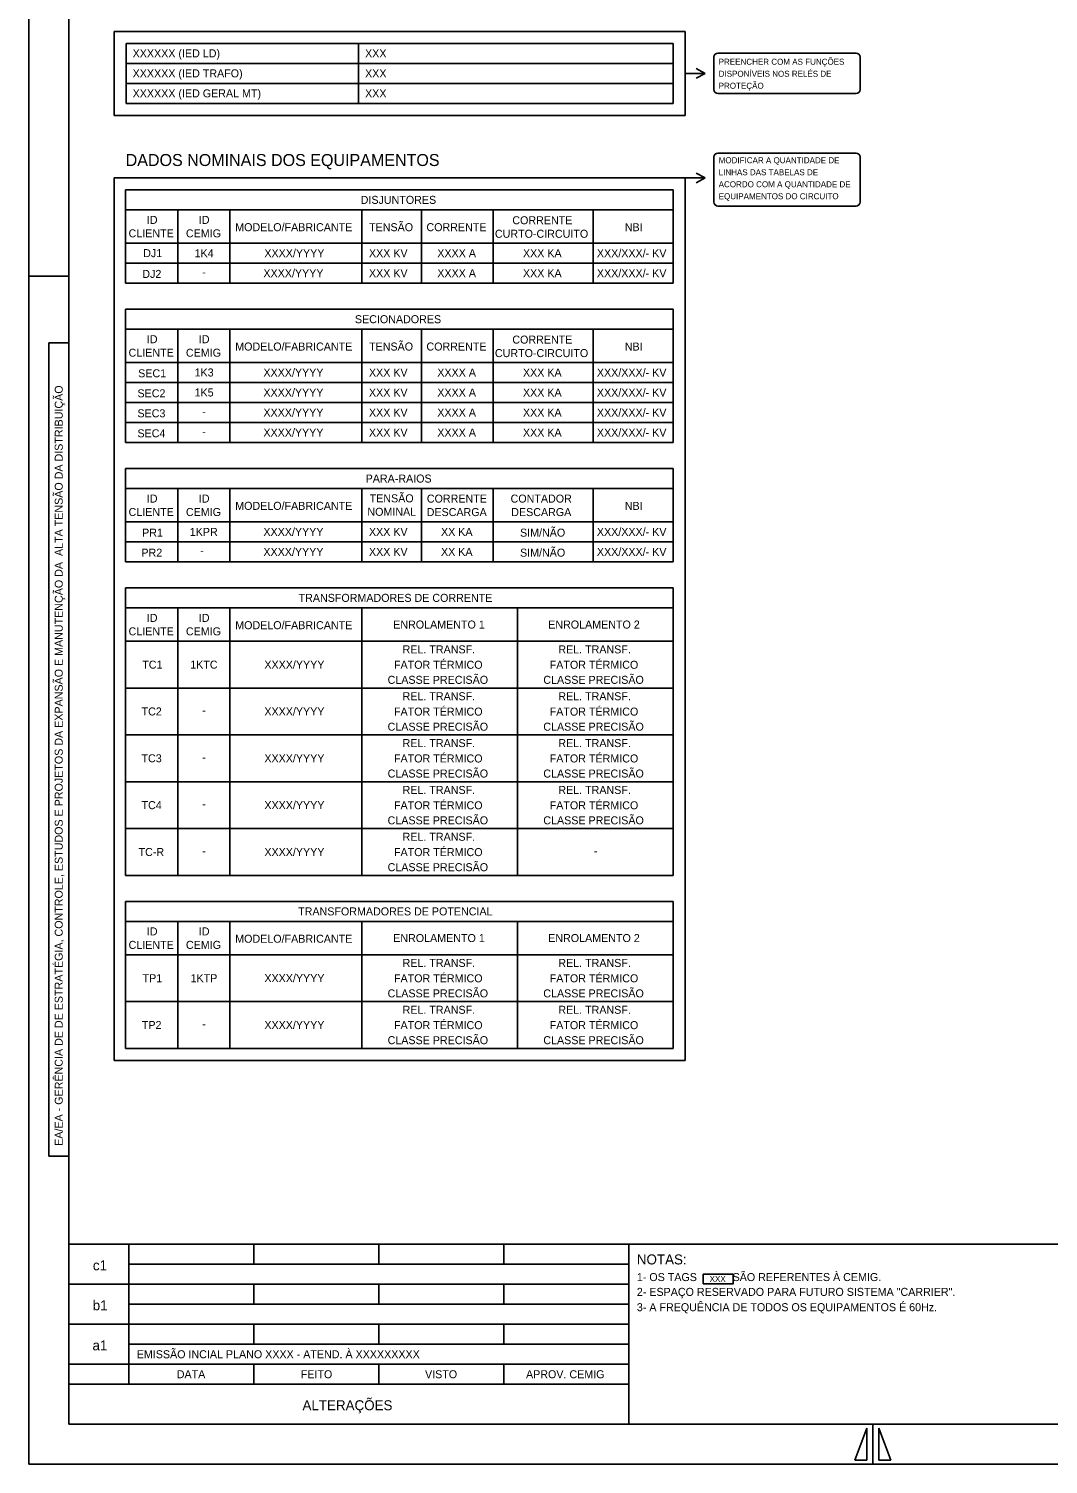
# Model space of a CAD drawing. Extents: x 563 to 1404, y 358 to 952.
# Drawn here: x 562.6 to 817.4, y 358 to 716.8 of the extents above; entities that cross this region are included whole.
import ezdxf

# ---------------------------------------------------------------- set-up
doc = ezdxf.new("R2010")
doc.units = 0
doc.layers.add('New Level (0)', color=7, linetype='Continuous')

# ---------------------------------------------------------------- blocks, each defined once
blk = doc.blocks.new('POINT_DISPLAY')
blk.add_line((0, 0), (0, 0))

msp = doc.modelspace()

# ---------------------------------------------------------------- linework, layer by layer
at = {"layer": 'New Level (0)'}
for p, q in [((562.58, 951.96), (562.58, 357.96)), ((562.58, 951.96), (562.58, 357.96)), ((572.58, 941.96), (572.58, 367.96)), ((572.58, 941.96), (572.58, 367.96)), ((583.96, 716.12), (726.65, 716.12)), ((583.96, 716.12), (583.96, 695.12)), ((726.65, 716.12), (726.65, 695.12)), ((586.96, 713.12), (723.65, 713.12)), ((586.96, 713.12), (586.96, 698.12)), ((645.01, 713.12), (645.01, 698.12)), ((723.65, 713.12), (723.65, 698.12)), ((734.84, 710.67), (742.19, 710.67)), ((742.19, 710.67), (769.38, 710.67)), ((586.96, 708.12), (723.65, 708.12)), ((733.84, 701.56), (733.84, 709.67)), ((770.38, 709.67), (770.38, 701.56)), ((726.65, 705.62), (731.68, 705.62)), ((731.68, 705.62), (729.38, 706.83)), ((731.68, 705.62), (729.38, 704.41)), ((586.96, 703.12), (723.65, 703.12)), ((769.38, 700.56), (734.84, 700.56)), ((586.96, 698.12), (723.65, 698.12)), ((583.96, 695.12), (726.65, 695.12)), ((734.84, 685.7), (742.19, 685.7)), ((742.19, 685.7), (769.38, 685.7)), ((733.84, 673.45), (733.84, 684.7)), ((770.38, 684.7), (770.38, 673.45)), ((583.96, 679.5), (583.96, 458.91)), ((583.96, 679.5), (726.65, 679.5)), ((726.65, 679.5), (726.65, 458.91)), ((726.65, 679.5), (731.68, 679.5)), ((731.68, 679.5), (729.38, 680.71)), ((731.68, 679.5), (729.38, 678.29)), ((586.81, 676.5), (586.81, 653.17)), ((586.81, 676.5), (723.65, 676.5)), ((723.65, 676.5), (723.65, 653.17)), ((723.65, 671.5), (586.81, 671.5)), ((599.81, 671.5), (599.81, 653.17)), ((612.81, 653.17), (612.81, 671.5)), ((645.81, 671.5), (645.81, 653.17)), ((660.72, 671.5), (660.72, 653.17)), ((678.66, 671.5), (678.66, 653.17)), ((703.66, 671.5), (703.66, 653.17)), ((769.38, 672.45), (734.84, 672.45)), ((586.81, 663.17), (723.65, 663.17)), ((586.81, 658.17), (723.65, 658.17)), ((562.58, 654.96), (572.58, 654.96)), ((586.81, 653.17), (723.65, 653.17)), ((586.81, 646.67), (586.81, 613.34)), ((586.81, 646.67), (723.65, 646.67)), ((723.65, 646.67), (723.65, 613.34)), ((723.65, 641.67), (586.81, 641.67)), ((599.81, 641.67), (599.81, 613.34)), ((612.81, 613.34), (612.81, 641.67)), ((645.81, 641.67), (645.81, 613.34)), ((660.72, 641.67), (660.72, 613.34)), ((678.66, 641.67), (678.66, 613.34)), ((703.66, 641.67), (703.66, 613.34)), ((567.58, 638.29), (572.58, 638.29)), ((567.58, 434.97), (567.58, 638.29)), ((586.81, 633.34), (723.65, 633.34)), ((586.81, 628.34), (723.65, 628.34)), ((586.81, 623.34), (723.65, 623.34)), ((586.81, 618.34), (723.65, 618.34)), ((586.81, 613.34), (723.65, 613.34)), ((586.81, 606.84), (586.81, 583.52)), ((586.81, 606.84), (723.65, 606.84)), ((723.65, 606.84), (723.65, 583.52)), ((723.65, 601.84), (586.81, 601.84)), ((599.81, 601.84), (599.81, 583.52)), ((612.81, 583.52), (612.81, 601.84)), ((645.81, 601.84), (645.81, 583.52)), ((660.72, 601.84), (660.72, 583.52)), ((678.66, 601.84), (678.66, 583.52)), ((703.66, 601.84), (703.66, 583.52)), ((586.81, 593.52), (723.65, 593.52)), ((629.06, 593.52), (723.65, 593.52)), ((586.81, 588.52), (723.65, 588.52)), ((586.81, 583.52), (723.65, 583.52)), ((586.81, 577.02), (586.81, 505.15)), ((586.81, 577.02), (723.65, 577.02)), ((723.65, 577.02), (723.65, 505.15)), ((723.65, 572.02), (586.81, 572.02)), ((599.81, 572.02), (599.81, 505.15)), ((612.81, 505.15), (612.81, 572.02)), ((645.81, 572.02), (645.81, 505.15)), ((684.73, 572.02), (684.73, 505.15)), ((586.81, 563.69), (723.65, 563.69)), ((586.81, 551.98), (723.65, 551.98)), ((586.81, 540.27), (723.65, 540.27)), ((586.81, 528.57), (723.65, 528.57)), ((586.81, 516.86), (723.65, 516.86)), ((586.81, 505.15), (723.65, 505.15)), ((586.81, 498.65), (586.81, 461.91)), ((586.81, 498.65), (723.65, 498.65)), ((723.65, 498.65), (723.65, 461.91)), ((723.65, 493.65), (586.81, 493.65)), ((599.81, 493.65), (599.81, 461.91)), ((612.81, 461.91), (612.81, 493.65)), ((645.81, 493.65), (645.81, 461.91)), ((684.73, 493.65), (684.73, 461.91)), ((586.81, 485.32), (723.65, 485.32)), ((586.81, 473.61), (723.65, 473.61)), ((586.81, 461.91), (723.65, 461.91)), ((726.65, 458.91), (583.96, 458.91)), ((572.58, 434.97), (567.58, 434.97)), ((572.58, 412.96), (1393.58, 412.96)), ((587.58, 377.96), (587.58, 412.96)), ((618.83, 407.96), (618.83, 412.96)), ((650.08, 407.96), (650.08, 412.96)), ((681.33, 407.96), (681.33, 412.96)), ((712.58, 412.96), (712.58, 367.96)), ((587.58, 407.96), (712.58, 407.96)), ((572.58, 402.96), (712.58, 402.96)), ((618.83, 397.96), (618.83, 402.96)), ((650.08, 397.96), (650.08, 402.96)), ((681.33, 397.96), (681.33, 402.96)), ((587.58, 397.96), (712.58, 397.96)), ((572.58, 392.96), (712.58, 392.96)), ((618.83, 387.96), (618.83, 392.96)), ((650.08, 387.96), (650.08, 392.96)), ((681.33, 387.96), (681.33, 392.96)), ((587.58, 387.96), (712.58, 387.96)), ((572.58, 382.96), (712.58, 382.96)), ((618.83, 377.96), (618.83, 382.96)), ((650.08, 377.96), (650.08, 382.96)), ((681.33, 377.96), (681.33, 382.96)), ((572.58, 377.96), (712.58, 377.96)), ((572.58, 367.96), (1393.58, 367.96)), ((572.58, 367.96), (1393.58, 367.96)), ((769.08, 358.96), (772.08, 366.96)), ((772.08, 366.96), (772.08, 358.96)), ((773.58, 367.96), (773.58, 357.96)), ((775.08, 366.96), (775.08, 358.96)), ((778.08, 358.96), (775.08, 366.96)), ((772.08, 358.96), (769.08, 358.96)), ((775.08, 358.96), (778.08, 358.96)), ((562.58, 357.96), (1403.58, 357.96)), ((562.58, 357.96), (1403.58, 357.96))]:
    msp.add_line(p, q, dxfattribs=at)
msp.add_lwpolyline([(731.16, 405.44), (738.67, 405.44), (738.67, 403.1), (731.16, 403.1)], close=True, dxfattribs=at)
for centre, start, end in [((734.84, 709.67), 90, 180), ((769.38, 709.67), 0, 90), ((734.84, 701.56), 180, 270), ((769.38, 701.56), 270, 0), ((734.84, 684.7), 90, 180), ((769.38, 684.7), 0, 90), ((734.84, 673.45), 180, 270), ((769.38, 673.45), 270, 0)]:
    msp.add_arc(centre, 1, start, end, dxfattribs=at)

# ---------------------------------------------------------------- block references
for p in [(670.01, 713.12), (655.23, 663.17), (655.23, 563.69), (655.23, 485.32)]:
    msp.add_blockref('POINT_DISPLAY', p, dxfattribs=at)

# ---------------------------------------------------------------- texts
for s, height, p in [('XXXXXX (IED LD)', 2, (588.55, 709.62)), ('XXX', 2, (646.65, 709.62)), ('PREENCHER COM AS FUNÇÕES ', 1.5, (735.03, 707.77)), ('XXXXXX (IED TRAFO)', 2, (588.55, 704.62)), ('XXX', 2, (646.65, 704.62)), ('DISPONÍVEIS NOS RELÉS DE ', 1.5, (735.03, 704.77)), ('PROTEÇÃO', 1.5, (735.03, 701.77)), ('XXXXXX (IED GERAL MT)', 2, (588.55, 699.62)), ('XXX', 2, (646.65, 699.62)), ('DADOS NOMINAIS DOS EQUIPAMENTOS', 3, (586.81, 682.46)), ('MODIFICAR A QUANTIDADE DE ', 1.5, (735.03, 683.15)), ('ACORDO COM A QUANTIDADE DE ', 1.5, (735.03, 677.15)), ('LINHAS DAS TABELAS DE ', 1.5, (735.03, 680.15)), ('DISJUNTORES', 2, (645.55, 673)), ('EQUIPAMENTOS DO CIRCUITO', 1.5, (735.03, 674.15)), ('ID', 2, (592.1, 668)), ('ID', 2, (605.1, 668)), ('MODELO/FABRICANTE', 2, (614.19, 666.17)), ('TENSÃO', 2, (647.65, 666.17)), ('CORRENTE', 2, (661.99, 666.17)), ('CORRENTE', 2, (683.46, 667.9)), ('NBI', 2, (711.56, 666.17)), ('CLIENTE', 2, (587.54, 664.63)), ('CEMIG', 2, (601.87, 664.63)), ('CURTO-CIRCUITO', 2, (679.1, 664.53)), ('DJ1', 2, (591.19, 659.68)), ('1K4', 2, (604.05, 659.67)), ('XXXX/YYYY', 2, (621.48, 659.67)), ('XXX KV', 2, (647.62, 659.67)), ('XXXX A', 2, (664.7, 659.67)), ('XXX KA', 2, (686.11, 659.67)), ('XXX/XXX/- KV', 2, (704.59, 659.67)), ('XXXX/YYYY', 2, (621.24, 654.67)), ('XXX KV', 2, (647.62, 654.67)), ('XXXX A', 2, (664.7, 654.67)), ('XXX KA', 2, (686.11, 654.67)), ('XXX/XXX/- KV', 2, (704.59, 654.67)), ('DJ2', 2, (590.97, 654.49)), ('-', 2, (605.94, 654.95)), ('SECIONADORES', 2, (644.11, 643.17)), ('ID', 2, (592.1, 638.17)), ('ID', 2, (605.1, 638.17)), ('TENSÃO', 2, (647.65, 636.34)), ('CORRENTE', 2, (683.46, 638.07)), ('CLIENTE', 2, (587.54, 634.8)), ('CEMIG', 2, (601.87, 634.8)), ('MODELO/FABRICANTE', 2, (614.19, 636.34)), ('CORRENTE', 2, (661.99, 636.34)), ('CURTO-CIRCUITO', 2, (679.1, 634.7)), ('NBI', 2, (711.56, 636.34)), ('SEC1', 2, (589.94, 629.65)), ('1K3', 2, (604.04, 629.86)), ('XXXX/YYYY', 2, (621.24, 629.84)), ('XXX KV', 2, (647.62, 629.84)), ('XXXX A', 2, (664.7, 629.84)), ('XXX KA', 2, (686.11, 629.84)), ('XXX/XXX/- KV', 2, (704.59, 629.84)), ('SEC2', 2, (589.76, 624.65)), ('1K5', 2, (604.04, 624.86)), ('XXXX/YYYY', 2, (621.24, 624.84)), ('XXX KV', 2, (647.62, 624.84)), ('XXXX A', 2, (664.7, 624.84)), ('XXX KA', 2, (686.11, 624.84)), ('XXX/XXX/- KV', 2, (704.59, 624.84)), ('SEC3', 2, (589.75, 619.65)), ('-', 2, (605.94, 620.12)), ('XXXX/YYYY', 2, (621.24, 619.84)), ('XXX KV', 2, (647.62, 619.84)), ('XXXX A', 2, (664.7, 619.84)), ('XXX KA', 2, (686.11, 619.84)), ('XXX/XXX/- KV', 2, (704.59, 619.84)), ('SEC4', 2, (589.75, 614.65)), ('-', 2, (605.94, 615.12)), ('XXXX/YYYY', 2, (621.24, 614.84)), ('XXX KV', 2, (647.62, 614.84)), ('XXXX A', 2, (664.7, 614.84)), ('XXX KA', 2, (686.11, 614.84)), ('XXX/XXX/- KV', 2, (704.59, 614.84)), ('PARA-RAIOS', 2, (646.79, 603.34)), ('ID', 2, (592.1, 598.34)), ('ID', 2, (605.1, 598.34)), ('TENSÃO ', 2, (647.79, 598.4)), ('CORRENTE', 2, (662.09, 598.33)), ('CONTADOR', 2, (683.02, 598.33)), ('CLIENTE', 2, (587.54, 594.98)), ('CEMIG', 2, (601.87, 594.98)), ('MODELO/FABRICANTE', 2, (614.19, 596.52)), ('NOMINAL', 2, (647.23, 595.03)), ('DESCARGA', 2, (662.05, 594.96)), ('DESCARGA', 2, (683.19, 594.96)), ('NBI', 2, (711.56, 596.52)), ('XXXX/YYYY', 2, (621.24, 590.02)), ('SIM/NÃO', 2, (685.38, 589.82)), ('XXX/XXX/- KV', 2, (704.59, 590.02)), ('PR1', 2, (590.92, 589.82)), ('1KPR', 2, (602.83, 590.01)), ('XXX KV', 2, (647.62, 590.02)), ('XX KA', 2, (665.63, 590.02)), ('PR2', 2, (590.74, 584.82)), ('-', 2, (605.47, 585.29)), ('XXXX/YYYY', 2, (621.24, 585.02)), ('XXX KV', 2, (647.62, 585.02)), ('XX KA', 2, (665.63, 585.02)), ('SIM/NÃO', 2, (685.38, 584.82)), ('XXX/XXX/- KV', 2, (704.59, 585.02)), ('TRANSFORMADORES DE CORRENTE', 2, (630.03, 573.52)), ('CLIENTE', 2, (587.54, 565.15)), ('ID', 2, (592.1, 568.52)), ('CEMIG', 2, (601.87, 565.15)), ('ID', 2, (605.1, 568.52)), ('MODELO/FABRICANTE', 2, (614.19, 566.69)), ('ENROLAMENTO 1', 2, (653.68, 566.85)), ('ENROLAMENTO 2', 2, (692.42, 566.85)), ('REL. TRANSF.', 2, (656.03, 560.64)), ('REL. TRANSF.', 2, (694.95, 560.64)), ('TC1', 2, (590.96, 556.83)), ('1KTC', 2, (602.95, 556.83)), ('XXXX/YYYY', 2, (621.48, 556.83)), ('FATOR TÉRMICO', 2, (653.88, 556.8)), ('FATOR TÉRMICO', 2, (692.8, 556.8)), ('CLASSE PRECISÃO', 2, (652.28, 553.03)), ('CLASSE PRECISÃO', 2, (691.2, 553.03)), ('REL. TRANSF.', 2, (656.03, 548.93)), ('REL. TRANSF.', 2, (694.95, 548.93)), ('TC2', 2, (590.78, 545.13)), ('-', 2, (605.94, 545.4)), ('XXXX/YYYY', 2, (621.48, 545.13)), ('FATOR TÉRMICO', 2, (653.88, 545.09)), ('FATOR TÉRMICO', 2, (692.8, 545.09)), ('CLASSE PRECISÃO', 2, (652.28, 541.32)), ('CLASSE PRECISÃO', 2, (691.2, 541.32)), ('REL. TRANSF.', 2, (656.03, 537.22)), ('REL. TRANSF.', 2, (694.95, 537.22)), ('TC3', 2, (590.77, 533.42)), ('XXXX/YYYY', 2, (621.48, 533.42)), ('FATOR TÉRMICO', 2, (653.88, 533.38)), ('FATOR TÉRMICO', 2, (692.8, 533.38)), ('-', 2, (605.94, 533.7)), ('CLASSE PRECISÃO', 2, (652.28, 529.61)), ('CLASSE PRECISÃO', 2, (691.2, 529.61)), ('REL. TRANSF.', 2, (656.03, 525.51)), ('REL. TRANSF.', 2, (694.95, 525.51)), ('FATOR TÉRMICO', 2, (653.88, 521.67)), ('FATOR TÉRMICO', 2, (692.8, 521.67)), ('TC4', 2, (590.78, 521.71)), ('-', 2, (605.94, 521.99)), ('XXXX/YYYY', 2, (621.48, 521.71)), ('CLASSE PRECISÃO', 2, (652.28, 517.91)), ('CLASSE PRECISÃO', 2, (691.2, 517.91)), ('REL. TRANSF.', 2, (656.03, 513.81)), ('TC-R', 2, (590.03, 510)), ('-', 2, (605.94, 510.28)), ('XXXX/YYYY', 2, (621.48, 510)), ('FATOR TÉRMICO', 2, (653.88, 509.97)), ('-', 2, (703.81, 510.28)), ('CLASSE PRECISÃO', 2, (652.28, 506.2)), ('TRANSFORMADORES DE POTENCIAL', 2, (629.92, 495.15)), ('ID', 2, (592.1, 490.15)), ('ID', 2, (605.1, 490.15)), ('CLIENTE', 2, (587.54, 486.78)), ('CEMIG', 2, (601.87, 486.78)), ('MODELO/FABRICANTE', 2, (614.19, 488.32)), ('ENROLAMENTO 1', 2, (653.68, 488.49)), ('ENROLAMENTO 2', 2, (692.42, 488.49)), ('FATOR TÉRMICO', 2, (653.88, 478.43)), ('REL. TRANSF.', 2, (656.03, 482.27)), ('FATOR TÉRMICO', 2, (692.8, 478.43)), ('REL. TRANSF.', 2, (694.95, 482.27)), ('TP1', 2, (591.04, 478.46)), ('1KTP', 2, (603.03, 478.46)), ('XXXX/YYYY', 2, (621.48, 478.47)), ('CLASSE PRECISÃO', 2, (652.28, 474.66)), ('CLASSE PRECISÃO', 2, (691.2, 474.66)), ('REL. TRANSF.', 2, (656.03, 470.56)), ('REL. TRANSF.', 2, (694.95, 470.56)), ('TP2', 2, (590.86, 466.76)), ('-', 2, (605.94, 467.04)), ('XXXX/YYYY', 2, (621.48, 466.76)), ('FATOR TÉRMICO', 2, (653.88, 466.72)), ('FATOR TÉRMICO', 2, (692.8, 466.72)), ('CLASSE PRECISÃO', 2, (652.28, 462.96)), ('CLASSE PRECISÃO', 2, (691.2, 462.96)), ('XXX', 1.5, (732.77, 403.54))]:
    msp.add_text(s, height=height).set_placement(p)
msp.add_text('EA/EA - GERÊNCIA DE DE ESTRATÉGIA, CONTROLE, ESTUDOS E PROJETOS DA EXPANSÃO E MANUTENÇÃO DA  ALTA TENSÃO DA DISTRIBUIÇÃO', height=2, rotation=90, dxfattribs=at).set_placement((571.08, 437.56))
for s, height, p in [('NOTAS:', 2.5, (714.58, 407.91)), ('c1', 2.5, (578.62, 406.44)), ('1- OS TAGS            SÃO REFERENTES À CEMIG.', 2, (714.58, 403.75)), ('2- ESPAÇO RESERVADO PARA FUTURO SISTEMA "CARRIER".', 2, (714.58, 400.05)), ('b1', 2.5, (578.57, 396.44)), ('3- A FREQUÊNCIA DE TODOS OS EQUIPAMENTOS É 60Hz.', 2, (714.58, 396.22)), ('a1', 2.5, (578.52, 386.44)), ('EMISSÃO INCIAL PLANO XXXX - ATEND. À XXXXXXXXX', 2, (589.58, 384.46)), ('DATA', 2, (599.58, 379.46)), ('FEITO', 2, (630.58, 379.46)), ('VISTO', 2, (661.64, 379.46)), ('APROV. CEMIG', 2, (686.88, 379.46)), ('ALTERAÇÕES', 2.5, (631.01, 371.46))]:
    msp.add_text(s, height=height, dxfattribs=at).set_placement(p)

doc.saveas('drawing.dxf')
